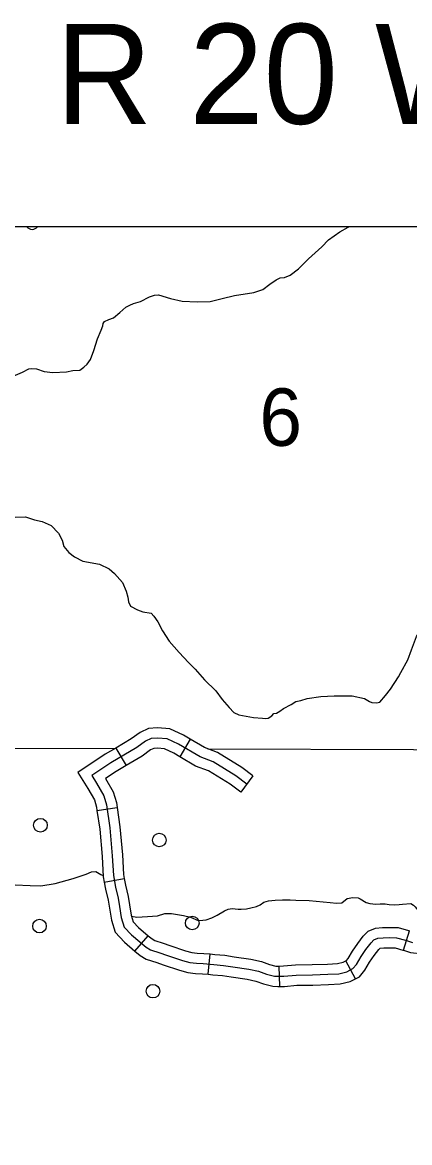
# Model space of a CAD drawing. Extents: x 1369979 to 1371646, y 379997 to 381064.
# Drawn here: x 1370923.4 to 1370956.8, y 380507.9 to 380604.5 of the extents above; entities that cross this region are included whole.
import ezdxf

# ---------------------------------------------------------------- set-up
doc = ezdxf.new("R2010")
doc.units = 0
for name, color, linetype in [('Default', 7, 'Continuous'), ('R_Border Notes', 7, 'Continuous'), ('R_No Plot', 7, 'Continuous')]:
    doc.layers.add(name, color=color, linetype=linetype)

msp = doc.modelspace()

# ---------------------------------------------------------------- linework, layer by layer
at = {"layer": 'R_Border Notes'}
for p, q in [((1370931.457, 380541.892), (1370932.354, 380540.381)), ((1370937.89, 380542.657), (1370936.994, 380541.145)), ((1370943.291, 380539.498), (1370942.235, 380538.092)), ((1370929.846, 380536.524), (1370931.586, 380536.774)), ((1370930.473, 380530.338), (1370932.202, 380530.656)), ((1370933.119, 380524.383), (1370934.261, 380525.719)), ((1370956.283, 380524.461), (1370956.796, 380526.142)), ((1370939.439, 380522.389), (1370939.589, 380524.141)), ((1370952.122, 380521.998), (1370951.29, 380523.547)), ((1370945.611, 380521.34), (1370945.565, 380523.097))]:
    msp.add_line(p, q, dxfattribs=at)
for points in [[(1370943.356, 380581.186), (1370944.131, 380581.427), (1370944.736, 380581.885), (1370945.298, 380582.269), (1370945.623, 380582.432), (1370946.007, 380582.462), (1370946.509, 380582.669), (1370947.232, 380583.23), (1370948.074, 380584.073), (1370949.226, 380585.123), (1370949.802, 380585.729), (1370950.792, 380586.394), (1370951.486, 380586.808), (1370951.648, 380586.867)], [(1370929.283, 380575.393), (1370929.561, 380576.189), (1370929.886, 380577.179), (1370930.211, 380577.919), (1370930.344, 380578.303), (1370930.373, 380578.495), (1370930.491, 380578.687), (1370930.861, 380578.835), (1370931.274, 380578.998), (1370931.806, 380579.456), (1370932.338, 380579.9), (1370932.663, 380580.077), (1370932.987, 380580.24), (1370933.593, 380580.387), (1370934.361, 380580.816), (1370934.789, 380580.949), (1370935.144, 380580.979), (1370936.192, 380580.654), (1370937.182, 380580.417), (1370938.482, 380580.358), (1370939.604, 380580.402), (1370940.638, 380580.654), (1370941.701, 380580.905), (1370943.356, 380581.186)], [(1370914.861, 380567.472), (1370915.316, 380567.656), (1370915.582, 380567.981), (1370915.656, 380568.276), (1370915.803, 380568.823), (1370915.951, 380569.459), (1370916.276, 380569.962), (1370916.719, 380570.42), (1370917.384, 380570.938), (1370918.107, 380571.455), (1370918.418, 380571.825), (1370918.772, 380572.268), (1370919.008, 380572.519), (1370919.407, 380572.815), (1370920.234, 380572.963), (1370920.884, 380573.259), (1370921.549, 380573.569), (1370922.036, 380573.702), (1370922.627, 380573.953), (1370923.41, 380574.293), (1370923.971, 380574.604), (1370924.163, 380574.634), (1370924.621, 380574.604)], [(1370924.621, 380574.604), (1370925.296, 380574.359), (1370926.049, 380574.27), (1370927.216, 380574.329), (1370927.777, 380574.447), (1370928.353, 380574.492), (1370928.722, 380574.728), (1370929.003, 380574.994), (1370929.283, 380575.393)], [(1370919.456, 380560.586), (1370920.315, 380561.154), (1370921.261, 380561.597), (1370922.029, 380561.789), (1370922.797, 380561.804), (1370923.668, 380561.834), (1370924.466, 380561.582), (1370925.115, 380561.42), (1370925.883, 380561.08), (1370926.518, 380560.429), (1370926.843, 380559.823), (1370926.991, 380559.276), (1370927.419, 380558.759), (1370927.892, 380558.374), (1370928.63, 380558.019), (1370930.048, 380557.739)], [(1370930.048, 380557.739), (1370930.886, 380557.351), (1370931.344, 380556.952), (1370932.038, 380556.183), (1370932.363, 380555.414), (1370932.496, 380554.912), (1370932.555, 380554.498), (1370932.747, 380554.143), (1370933.352, 380553.803), (1370933.795, 380553.655), (1370934.519, 380553.537), (1370934.741, 380553.271), (1370935.08, 380552.768), (1370935.479, 380551.999), (1370936.055, 380551.127), (1370936.941, 380550.122), (1370937.724, 380549.264)], [(1370956.651, 380549.495), (1370956.961, 380550.361), (1370957.404, 380551.529), (1370957.818, 380552.195), (1370958.305, 380552.682), (1370958.984, 380553.525), (1370960.314, 380554.456)], [(1370947.955, 380546.183), (1370949.148, 380546.346), (1370950.3, 380546.405), (1370951.851, 380546.405), (1370952.899, 380546.183), (1370953.343, 380545.917), (1370953.535, 380545.814), (1370953.948, 380545.784), (1370954.229, 380545.858), (1370954.731, 380546.435), (1370955.159, 380546.982), (1370955.839, 380548.046), (1370956.031, 380548.401), (1370956.651, 380549.495)], [(1370937.724, 380549.264), (1370938.296, 380548.697), (1370939.108, 380547.765), (1370940.097, 380546.819), (1370940.629, 380546.08), (1370941.249, 380545.4), (1370941.633, 380544.971), (1370942.062, 380544.749), (1370943.347, 380544.528), (1370944.1, 380544.468), (1370944.381, 380544.454), (1370944.602, 380544.483), (1370944.912, 380544.661), (1370945.104, 380544.868), (1370945.326, 380544.912), (1370945.621, 380545.075), (1370945.931, 380545.311), (1370946.596, 380545.666), (1370946.995, 380545.903), (1370947.408, 380546.006), (1370947.955, 380546.183)], [(1370942.763, 380538.795), (1370941.827, 380539.498), (1370939.849, 380540.722), (1370938.731, 380541.138), (1370936.884, 380542.232), (1370935.895, 380542.701), (1370935.063, 380542.753), (1370934.516, 380542.727), (1370934.022, 380542.492), (1370933.268, 380541.946), (1370931.03, 380540.617), (1370929.391, 380539.524), (1370929.808, 380538.873), (1370930.432, 380537.779), (1370930.666, 380536.998), (1370930.952, 380535.008)], [(1370937.89, 380542.657), (1370937.297, 380543.009), (1370936.119, 380543.567), (1370935.069, 380543.633), (1370934.299, 380543.596), (1370933.572, 380543.252), (1370932.784, 380542.681), (1370931.457, 380541.892)], [(1370919.771, 380541.901), (1370931.397, 380541.857)], [(1370931.457, 380541.892), (1370930.562, 380541.361), (1370928.187, 380539.776), (1370929.055, 380538.418), (1370929.619, 380537.431), (1370929.806, 380536.808), (1370929.846, 380536.524)], [(1370936.994, 380541.145), (1370936.471, 380541.455), (1370935.671, 380541.834), (1370935.056, 380541.873), (1370934.734, 380541.857), (1370934.472, 380541.733), (1370933.751, 380541.21), (1370932.354, 380540.381)], [(1370943.291, 380539.498), (1370942.323, 380540.224), (1370940.238, 380541.515), (1370939.111, 380541.935), (1370937.89, 380542.657)], [(1370939.399, 380541.827), (1370957.125, 380541.761), (1370962.639, 380541.699)], [(1370942.235, 380538.092), (1370941.33, 380538.771), (1370939.461, 380539.928), (1370938.35, 380540.342), (1370936.994, 380541.145)], [(1370932.354, 380540.381), (1370931.499, 380539.874), (1370930.593, 380539.269), (1370931.245, 380538.128), (1370931.527, 380537.188), (1370931.586, 380536.774)], [(1370929.846, 380536.524), (1370930.079, 380534.908), (1370930.284, 380532.548), (1370930.391, 380530.788), (1370930.473, 380530.338)], [(1370931.586, 380536.774), (1370931.826, 380535.109), (1370932.037, 380532.677), (1370932.139, 380531.001), (1370932.202, 380530.656)], [(1370930.952, 380535.008), (1370931.161, 380532.613), (1370931.265, 380530.894), (1370931.447, 380529.905), (1370931.681, 380528.941), (1370931.785, 380528.238), (1370931.941, 380527.274), (1370932.201, 380526.467), (1370932.825, 380525.79), (1370934.074, 380524.723)], [(1370919.327, 380530.185), (1370920.993, 380530.249), (1370922.78, 380530.116), (1370924.08, 380530.042), (1370925.01, 380530.013), (1370926.251, 380530.205), (1370927.787, 380530.663), (1370928.924, 380531.033), (1370929.382, 380531.225), (1370929.737, 380531.24), (1370930.165, 380531.003), (1370930.367, 380530.913)], [(1370930.473, 380530.338), (1370930.587, 380529.721), (1370930.817, 380528.773), (1370930.916, 380528.103), (1370931.084, 380527.068), (1370931.424, 380526.014), (1370932.215, 380525.156), (1370933.119, 380524.383)], [(1370932.202, 380530.656), (1370932.307, 380530.088), (1370932.544, 380529.11), (1370932.653, 380528.373), (1370932.798, 380527.481), (1370932.978, 380526.921), (1370933.436, 380526.424), (1370934.261, 380525.719)], [(1370935.699, 380527.633), (1370936.272, 380527.633), (1370937.306, 380527.47), (1370937.911, 380527.307), (1370938.561, 380527.041), (1370938.975, 380527.056), (1370939.256, 380527.071), (1370939.743, 380527.263), (1370940.216, 380527.499), (1370940.851, 380527.869), (1370941.161, 380528.002), (1370941.486, 380528.061), (1370942.017, 380528.017), (1370942.268, 380528.002), (1370942.726, 380528.046), (1370943.096, 380528.106), (1370943.583, 380528.224), (1370943.923, 380528.387), (1370944.233, 380528.608), (1370944.632, 380528.727), (1370945.193, 380528.771), (1370945.843, 380528.815)], [(1370945.843, 380528.815), (1370946.503, 380528.815), (1370946.99, 380528.786), (1370948.127, 380528.741), (1370949.944, 380528.593), (1370950.505, 380528.534), (1370950.963, 380528.564), (1370951.421, 380528.919), (1370951.908, 380529.022), (1370952.351, 380528.978), (1370952.543, 380528.904), (1370953.046, 380528.579), (1370953.371, 380528.505), (1370953.888, 380528.446), (1370954.272, 380528.46), (1370954.7, 380528.46), (1370955.025, 380528.416), (1370955.468, 380528.387), (1370955.896, 380528.401), (1370956.192, 380528.431)], [(1370956.192, 380528.431), (1370956.896, 380528.48), (1370957.132, 380528.347), (1370957.28, 380528.199), (1370957.767, 380527.607), (1370958.225, 380527.12), (1370958.787, 380526.661), (1370959.555, 380526.203), (1370960.529, 380525.715)], [(1370932.811, 380527.4), (1370933.277, 380527.322), (1370934.193, 380527.366), (1370935.049, 380527.426), (1370935.699, 380527.633)], [(1370951.29, 380523.547), (1370951.344, 380523.575), (1370951.496, 380523.753), (1370951.868, 380524.397), (1370952.329, 380525.04), (1370952.807, 380525.674), (1370953.225, 380526.115), (1370953.865, 380526.361), (1370954.47, 380526.413), (1370955.077, 380526.427), (1370955.8, 380526.411), (1370956.698, 380526.172), (1370956.796, 380526.142)], [(1370934.261, 380525.719), (1370934.59, 380525.438), (1370934.82, 380525.3), (1370935.554, 380525.067), (1370936.114, 380524.87), (1370937.468, 380524.422), (1370938.018, 380524.265), (1370938.488, 380524.211), (1370939.061, 380524.186), (1370939.589, 380524.141)], [(1370941.551, 380523.035), (1370942.943, 380522.827), (1370943.775, 380522.645), (1370944.465, 380522.397), (1370945.141, 380522.228), (1370945.453, 380522.215), (1370945.961, 380522.228), (1370947.014, 380522.319), (1370948.432, 380522.345), (1370949.759, 380522.397), (1370950.695, 380522.436), (1370951.372, 380522.592), (1370951.905, 380522.879), (1370952.217, 380523.243), (1370952.607, 380523.92), (1370953.037, 380524.519), (1370953.479, 380525.105), (1370953.726, 380525.366), (1370954.064, 380525.496), (1370954.518, 380525.535), (1370955.077, 380525.548), (1370955.676, 380525.535), (1370956.456, 380525.327), (1370957.055, 380525.144)], [(1370933.119, 380524.383), (1370933.559, 380524.007), (1370934.091, 380523.687), (1370934.996, 380523.399), (1370935.547, 380523.206), (1370936.95, 380522.742), (1370937.675, 380522.535), (1370938.35, 380522.458), (1370938.947, 380522.431), (1370939.439, 380522.389)], [(1370934.074, 380524.723), (1370934.456, 380524.493), (1370935.275, 380524.233), (1370935.83, 380524.038), (1370937.209, 380523.582), (1370937.847, 380523.4), (1370938.419, 380523.335), (1370939.004, 380523.309), (1370939.915, 380523.23), (1370940.76, 380523.152), (1370941.551, 380523.035)], [(1370952.122, 380521.998), (1370952.466, 380522.182), (1370952.938, 380522.734), (1370953.347, 380523.444), (1370953.745, 380523.999), (1370954.15, 380524.536), (1370954.227, 380524.617), (1370954.264, 380524.631), (1370954.566, 380524.657), (1370955.078, 380524.669), (1370955.551, 380524.659), (1370956.215, 380524.481), (1370956.283, 380524.461)], [(1370956.283, 380524.461), (1370956.872, 380524.281), (1370957.942, 380524.151), (1370958.642, 380524.115), (1370958.847, 380524.058), (1370959.054, 380523.986), (1370959.302, 380523.82), (1370959.526, 380523.578), (1370959.719, 380523.343), (1370959.825, 380523.066), (1370959.912, 380522.379), (1370959.935, 380522.012)], [(1370939.589, 380524.141), (1370939.993, 380524.106), (1370940.865, 380524.025), (1370941.681, 380523.904), (1370943.102, 380523.692), (1370944.019, 380523.491), (1370944.72, 380523.239), (1370945.267, 380523.102), (1370945.46, 380523.094), (1370945.565, 380523.097)], [(1370945.565, 380523.097), (1370945.911, 380523.106), (1370946.968, 380523.197), (1370948.407, 380523.224), (1370949.723, 380523.275), (1370950.577, 380523.311), (1370951.059, 380523.422), (1370951.29, 380523.547)], [(1370939.439, 380522.389), (1370939.837, 380522.355), (1370940.655, 380522.279), (1370941.422, 380522.166), (1370942.784, 380521.962), (1370943.532, 380521.798), (1370944.209, 380521.555), (1370945.015, 380521.353), (1370945.446, 380521.336), (1370945.611, 380521.34)], [(1370945.611, 380521.34), (1370946.01, 380521.35), (1370947.06, 380521.441), (1370948.457, 380521.466), (1370949.794, 380521.519), (1370950.813, 380521.561), (1370951.684, 380521.763), (1370952.122, 380521.998)]]:
    msp.add_lwpolyline(points, dxfattribs=at)
for centre in [(1370924.969, 380535.24), (1370935.219, 380533.964), (1370938.055, 380526.811), (1370924.891, 380526.543), (1370934.672, 380520.932)]:
    msp.add_circle(centre, 0.586, dxfattribs=at)
msp.add_arc((1370924.257, 380587.206), 0.586, 215.24494, 324.75506, dxfattribs=at)
at = {"layer": 'R_No Plot'}
msp.add_lwpolyline([(1370544.495, 380586.867), (1371140.383, 380586.867), (1371140.383, 380146.391), (1370544.495, 380146.391)], close=True, dxfattribs=at)

# ---------------------------------------------------------------- texts
at = {"layer": 'Default'}
msp.add_text('R 20 W', height=8.6181, dxfattribs=at).set_placement((1370926.275, 380595.718))
at = {"layer": 'R_Border Notes'}
msp.add_text('6', height=4.95, dxfattribs=at).set_placement((1370943.844, 380567.958))

doc.saveas('drawing.dxf')
